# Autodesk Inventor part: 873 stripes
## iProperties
Author: Vincent Molino
Shininess: 24.0
Angle Display Precision: 2
Document Length Units: 11272
Document Angle Units: 11286
Document Time Units: 11279
Document Mass Units: 11290
Document Length Units Precision: 3
Document Angle Units Precision: 2
Compacted: True
PropertySet Name: _Private Model Information
Created: 2002-05
Part Number: 873 stripes
Document SubType Name: Modeling
Designer: Vincent Molino
Control State: 0
Master: False
Checked Out: False
PropertySet Name: Design Tracking Control
Density: 0.0
Volumn: 0.0
Area: 0.0
PropertySet Name: Model Information
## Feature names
1. Extrusion1
